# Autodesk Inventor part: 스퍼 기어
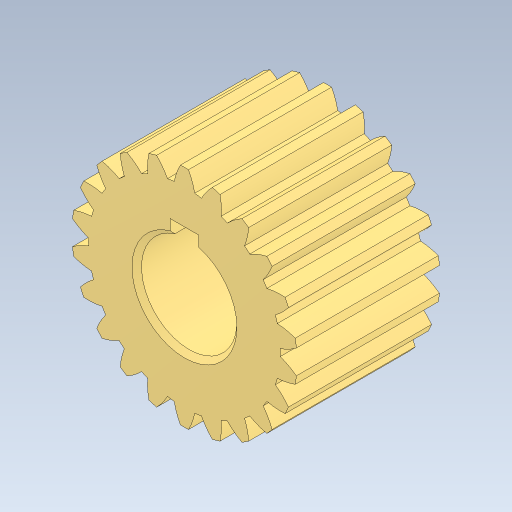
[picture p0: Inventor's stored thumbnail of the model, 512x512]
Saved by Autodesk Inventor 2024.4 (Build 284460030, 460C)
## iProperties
Created: 2026-09
Part Number: 스퍼 기어
Material: 강철, 합금
Document SubType Name: Modeling
Designer: user
Density: 7.73 g/cm^3
Appearance: 기본값
Author: jhkim
Sending System: Autodesk Inventor 2027
Preprocessor: ST-DEVELOPER v20.1
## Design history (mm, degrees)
feature "Solid1"
node "솔리드1"
